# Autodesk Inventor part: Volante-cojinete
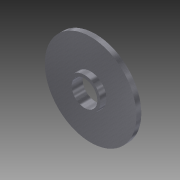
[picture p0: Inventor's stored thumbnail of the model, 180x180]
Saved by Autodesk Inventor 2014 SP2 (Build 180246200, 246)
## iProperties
Created: 2015-10
Part Number: Volante-cojinete
Material: Acero, aleación
Document SubType Name: Modeling
Designer: Jaime
Mass: 10000 g
Surface Area: 403.506 cm^2
Volume: 137.671 cm^3
Density: 72.637 g/cm^3
Appearance: Mecanizado 02
Author: Jaime
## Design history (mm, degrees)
sketch "Boceto1"
  geometry: L1 (-4.377, 0)-(4.377, 0); L2 (-10, 26)-(0, 26); L3 (0, 26)-(0, 75); L4 (0, 75)-(8, 75); L5 (8, 75)-(8, 21); L6 (8, 21)-(-10, 21); L7 (-10, 21)-(-10, 26); 3 further points
  constraints: 14 end point, 3 parallel, 3 perpendicular, 2 coincident, 2 midpoint, 1 horizontal, 1 vertical alignment
  dimensions: "d0" = 42 diameter of L6 L1; "d1" = 52 diameter of L2 L1; "d3" = 150 diameter of L4 L1; "d4" = 8 distance of L3.end L4.end; "d5" = 10 distance of L2.start L2.end
revolve "Revolución1" sketch "Boceto1" stored, may be unused: angle "d6" = 90 deg
node "Sólido1"
